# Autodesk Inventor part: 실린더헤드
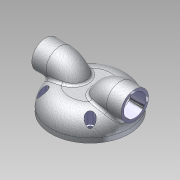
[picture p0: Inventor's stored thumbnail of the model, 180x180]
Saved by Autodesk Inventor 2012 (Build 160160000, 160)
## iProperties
Manager: KYOUNG IL JANG
Company: 한국ATC센터
Created: 2012-10
Part Number: 실린더헤드
Document SubType Name: Modeling
Density: 1 g/cm^3
Checked By: KYOUNG IL JANG
Vendor: CBT Solutions
Designer: KYOUNG IL JANG
Material: 기본값
Author: KYOUNG IL JANG
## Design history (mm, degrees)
sketch "스케치1"
  geometry: C1 r 42.5 at (0, 0); 1 further point
  constraints: 1 centre point, 1 coincident
  dimensions: "d0" = 85 diameter of C1
extrude "돌출1" new body sketch "스케치1" distance "d1" = 25; taper "d2" = 0 deg
fillet "모깎기1" dims "d3" = 20
sketch "스케치2"
  geometry: C1 r 30 at (0, 0); 1 further point
  constraints: 1 centre point, 1 coincident
  dimensions: "d4" = 60 diameter of C1
extrude "돌출2" join sketch "스케치2" distance "d5" = 5; taper "d6" = 0 deg
sketch "스케치3"
  geometry: L1 (-42.5, 0)-(42.5, 0) reference; L2 (-48.5, 30)-(-33, 30); L3 (-17.545, 18.141)-(-12.684, 0); A1 r 16 centre (-33, 14) between (-17.545, 18.141) and (-33, 30); 1 further point
  constraints: 4 end point, 2 point on circle, 2 tangent, 1 centre point, 1 parallel, 1 point on line
  dimensions: "d7" = 16 radius of A1; "d8" = 6 horizontal distance of L2.start L1.start; "d9" = 30 distance between parallel lines of L2 L1; "d11" = 105 deg angle of L3 L1; "d36" = 15.5 distance of L2.start L2.end
node "작업 평면1"
sketch "스케치4"
  geometry: C1 r 15 at (0, 0); C2 r 12 at (0, 0); 2 further points
  constraints: 2 centre point, 2 coincident
  dimensions: "d12" = 30 diameter of C1; "d13" = 3 radial gap between concentric circles of C2 C1
feature "스윕1" dims "d14" = 0
feature "스윕2" dims "d15" = 0
sketch "스케치5"
  geometry: L1 (30, -5)-(-30, -5) reference; L2 (0, -5)-(0, 10); L3 (0, 10)-(-10, 10); A1 r 15 centre (-10, -5) between (-10, 10) and (-25, -5); 1 further point
  constraints: 4 end point, 2 perpendicular, 2 point on circle, 1 centre point, 1 midpoint, 1 point on line, 1 tangent
  dimensions: "d16" = 15 distance of L2.start L2.end; "d17" = 15 radius of A1; "d18" = 5 distance of L1.end A1.end
revolve "회전1" sketch "스케치5" stored, may be unused: angle "d19" = 90 deg
fillet "모깎기2" dims "d20" = 3
node "작업 평면2"
sketch "스케치6"
  geometry: L1 (0, 0)-(36.25, 0); C1 r 4.75 at (25.633, 25.633); C2 r 2.75 at (25.633, 25.633); A1 r 36.25 centre (0, 0) between (25.633, 25.633) and (36.25, 0); 1 further point
  constraints: 3 centre point, 2 coincident, 2 end point, 2 point on circle, 1 horizontal
  dimensions: "d22" = 72.5 diameter of A1; "d23" = 5.5 diameter of C2; "d24" = 9.5 diameter of C1; "d37" = 45 deg dimension on point (0, 0) C1.centre L1.end
extrude "돌출3" cut sketch "스케치6" stored distance "d25" = 5; taper "d26" = 0 deg
extrude "돌출4" cut sketch "스케치6" stored distance "d27" = 5; taper "d28" = 0 deg
chamfer "모따기1" distance "d33" = 1; stored, may be unused: second distance "d34" = 2, angle "d35" = 45 deg
node "솔리드1"
mirror "대칭1"
pattern_circular "원형 패턴1" dims angle "d30" = 360 deg
